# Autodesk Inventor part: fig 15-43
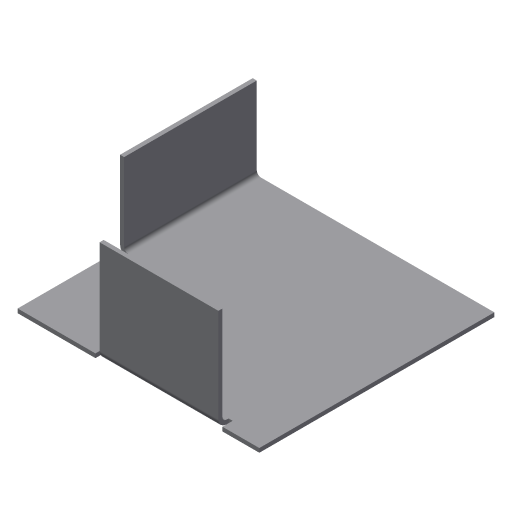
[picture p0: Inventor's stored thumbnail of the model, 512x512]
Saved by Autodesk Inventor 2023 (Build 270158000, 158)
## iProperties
Created: 2005-03
Part Number: fig 15-43
Document SubType Name: Sheet Metal
Designer: CADCIM
Manufacturer: Standard
Standards Organization: Custom
Density: 1 g/cm^3
Sheet Metal Rule: Default
Material: Generic
Appearance: Default
Author: CADCIM
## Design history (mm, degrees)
node "Face1"
  sketch "Sketch1"
    geometry: L1 (-29, -26)-(30, -26); L2 (30, -26)-(30, 31.375); L3 (30, 31.375)-(-29, 31.375); L4 (-29, 31.375)-(-29, -26)
    constraints: 8 end point, 2 parallel, 1 horizontal, 1 perpendicular
node "Flange1"
node "Flange3"
body "Solid1"
face "Plate1" dims "d21" = 1 (= Thickness)
sketch "Sketch2"
  geometry: L1 (25, 0)-(57.375, 0); L2 (57.375, 0)-(57.375, 20); L3 (57.375, 20)-(25, 20); L4 (25, 20)-(25, 0)
  constraints: 8 end point
face "Plate2" dims "d1" = 0, "d2" = 25, "d3" = 1 (= BendReliefWidth), "d5" = 2 (= MinimumRemnant), "d7" = 20, "d8" = 90 deg, "d9" = 1 (= BendRadius), "d21" = 1 (= Thickness)
bend "Bend1" dims "d3" = 1 (= BendReliefWidth), "d4" = 0.5 (= BendReliefDepth), "d5" = 2 (= MinimumRemnant), "d6" = 1 (= BendRadius), "d7" = 20, "d8" = 90 deg, "d9" = 1 (= BendRadius), "d21" = 1 (= Thickness), "SeamGap" = 0.01
sketch "Sketch4"
  geometry: L1 (-39, 0)-(-10, 0); L2 (-10, 0)-(-10, 25); L3 (-10, 25)-(-39, 25); L4 (-39, 25)-(-39, 0)
  constraints: 8 end point
face "Plate4" dims "d21" = 1 (= Thickness), "d22" = 1 (= BendReliefWidth), "d23" = 0.5 (= BendReliefDepth), "d24" = 2 (= MinimumRemnant), "d25" = 1 (= TransitionRadius), "d26" = 20, "d27" = 10, "d28" = 25, "d29" = 90 deg, "d30" = 1 (= BendRadius), "d31" = 4 (= CornerReliefSize), "d32" = 1 (= GapSize), "d33" = 1 (= JacobiRadiusSize), "SeamGap" = 0.01
bend "Bend3" dims "d21" = 1 (= Thickness), "d22" = 1 (= BendReliefWidth), "d23" = 0.5 (= BendReliefDepth), "d24" = 2 (= MinimumRemnant), "d25" = 1 (= TransitionRadius), "d28" = 25, "d29" = 90 deg, "d30" = 1 (= BendRadius), "SeamGap" = 0.01
feature "Corner1" dims "d28" = 25, "d29" = 90 deg, "d31" = 4 (= CornerReliefSize), "d32" = 1 (= GapSize), "d33" = 1 (= JacobiRadiusSize)
other parameters: "Thickness" = 1, "BendRadius" = 1 (= Thickness), "BendReliefWidth" = 1 (= Thickness), "BendReliefDepth" = 0.5 (= 0.5 x Thickness), "CornerReliefSize" = 4 (= 4 x Thickness), "MinimumRemnant" = 2 (= 2 x Thickness), "TransitionRadius" = 1 (= BendRadius), "d0" = 1 (= BendRadius), "JacobiRadiusSize" = 1 (= Thickness), "GapSize" = 1 (= Thickness)
